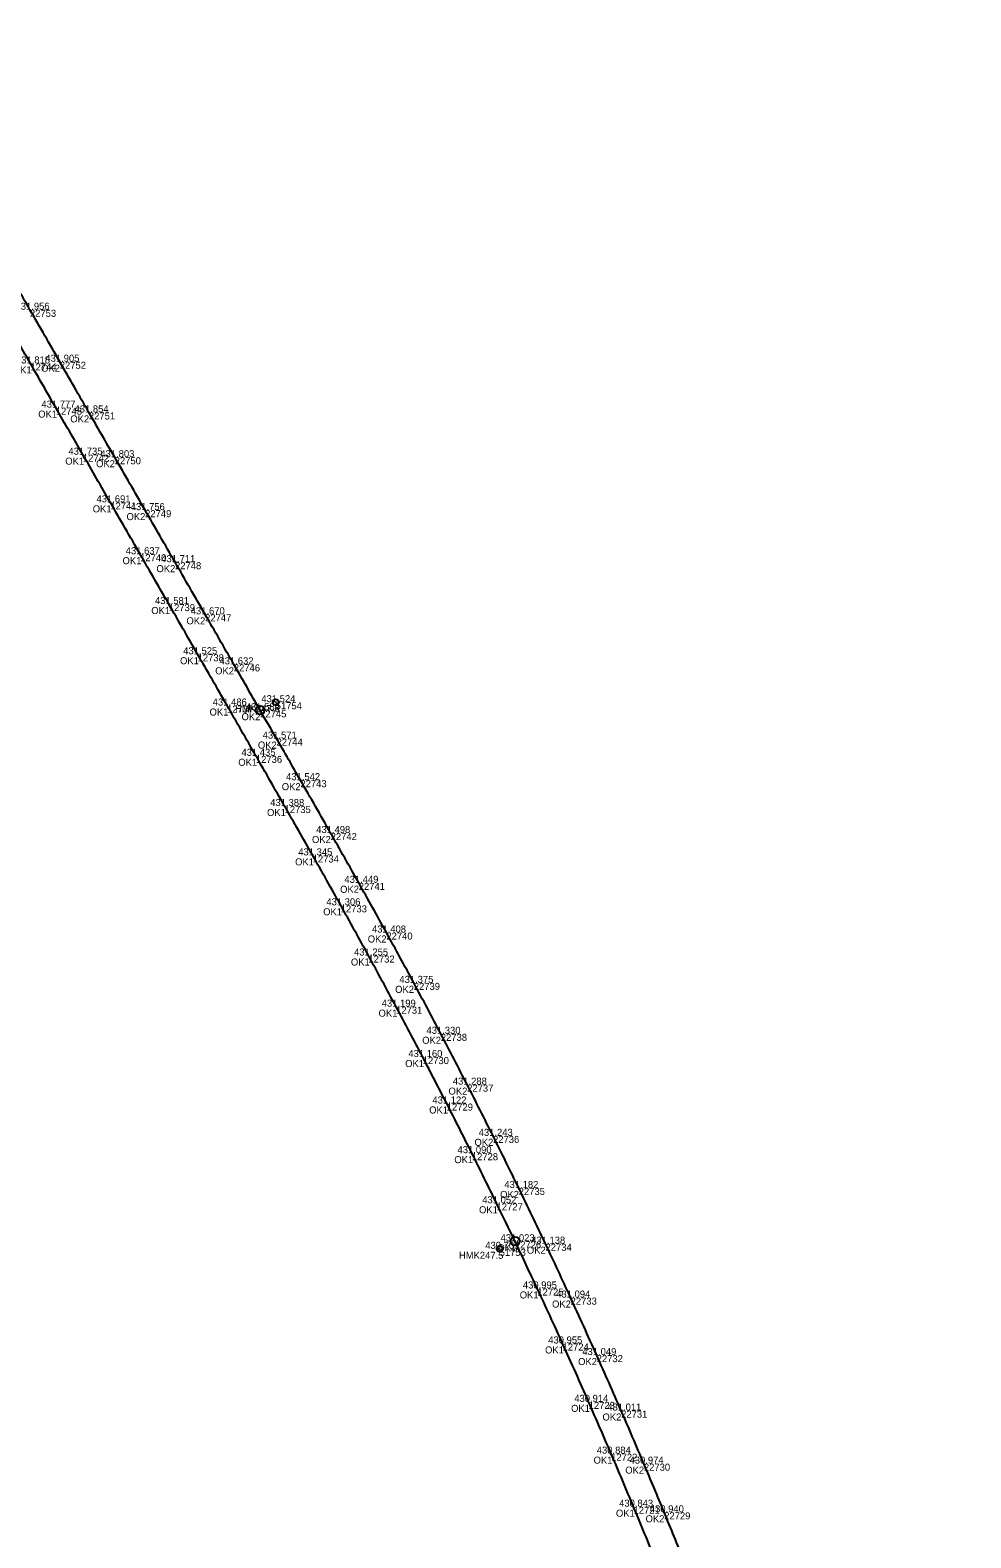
# Model space of a CAD drawing. Extents: x -678609 to -677678, y -1092434 to -1090394.
# Drawn here: x -678281 to -678120.7, y -1091923.5 to -1091666.6 of the extents above; entities that cross this region are included whole.
import ezdxf

# ---------------------------------------------------------------- set-up
doc = ezdxf.new("R2010")
doc.units = 0
for name, color, linetype in [('Vrstva 1', 7, 'Continuous'), ('Vrstva 60', 7, 'Continuous'), ('Vrstva 61', 7, 'Continuous'), ('Vrstva 62', 7, 'Continuous'), ('Vrstva 7', 7, 'Continuous')]:
    doc.layers.add(name, color=color, linetype=linetype)

msp = doc.modelspace()

# ---------------------------------------------------------------- linework, layer by layer
at = {"layer": 'Vrstva 1'}
for points in [[(-677965.5, -1092428.88), (-677967.8, -1092425.54), (-677972.06, -1092419.07), (-677977.32, -1092410.57), (-677981.84, -1092402.75), (-677986.7, -1092393.7), (-677991.48, -1092384.16), (-677995.99, -1092374.55), (-678000.17, -1092365.13), (-678004.02, -1092356.1), (-678007.82, -1092346.9), (-678011.74, -1092337.16), (-678015.49, -1092327.76), (-678018.88, -1092319.21), (-678022.34, -1092310.49), (-678025.4, -1092302.78), (-678026.46, -1092300.1), (-678028.08, -1092296.04), (-678031.51, -1092287.37), (-678035.08, -1092278.36), (-678038.67, -1092269.33), (-678042.19, -1092260.44), (-678045.92, -1092251.04), (-678049.17, -1092242.84), (-678052.72, -1092233.88), (-678056.52, -1092224.29), (-678060.13, -1092215.17), (-678063.85, -1092205.78), (-678067.58, -1092196.38), (-678071.23, -1092187.17), (-678074.63, -1092178.59), (-678078.07, -1092169.9), (-678081.19, -1092162.05), (-678084.71, -1092153.16), (-678085.21, -1092151.9), (-678088.66, -1092143.2), (-678090.49, -1092138.62), (-678093.75, -1092130.39), (-678097.35, -1092121.32), (-678101.03, -1092112.07), (-678104.65, -1092102.94), (-678108.08, -1092094.3), (-678111.85, -1092084.82), (-678115.34, -1092076.03), (-678118.88, -1092067.13), (-678122.7, -1092057.52), (-678126.45, -1092048.08), (-678130.12, -1092038.85), (-678134.04, -1092029), (-678137.7, -1092019.78), (-678141.32, -1092010.68), (-678144.94, -1092001.55), (-678148.54, -1091992.51), (-678152.22, -1091983.22), (-678155.78, -1091974.26), (-678159.37, -1091965.23), (-678163.15, -1091955.67), (-678166.8, -1091946.49), (-678170.64, -1091936.84), (-678174.45, -1091927.39), (-678178.21, -1091918.23), (-678182.03, -1091909.19), (-678185.86, -1091900.36), (-678190.3, -1091890.41), (-678194.61, -1091881.04), (-678198.42, -1091872.99), (-678201.55, -1091866.52), (-678205.76, -1091857.98), (-678210.04, -1091849.52), (-678214.14, -1091841.6), (-678218.68, -1091833.02), (-678223.39, -1091824.3), (-678228.11, -1091815.74), (-678232.89, -1091807.24), (-678237.68, -1091798.82), (-678242.57, -1091790.27), (-678247.48, -1091781.7), (-678252.5, -1091772.96), (-678257.41, -1091764.41), (-678262.3, -1091755.91), (-678267.38, -1091747.08), (-678272.06, -1091738.95), (-678276.67, -1091730.93), (-678281, -1091723.4), (-678285.64, -1091715.33), (-678290.57, -1091706.75), (-678295.17, -1091698.74), (-678299.18, -1091691.75), (-678304.61, -1091682.28), (-678309.18, -1091674.33), (-678309.94, -1091673.01), (-678310.56, -1091671.92), (-678316.58, -1091661.44), (-678321.55, -1091652.79), (-678326.07, -1091644.94), (-678331.1, -1091636.19), (-678336.13, -1091627.42), (-678341.16, -1091618.67), (-678346.24, -1091609.83), (-678351.2, -1091601.19), (-678356.26, -1091592.39), (-678361.27, -1091583.68), (-678366.29, -1091574.95), (-678371.38, -1091566.09), (-678376.48, -1091557.23), (-678380.94, -1091549.47), (-678384.95, -1091542.5), (-678389.88, -1091533.92), (-678391.41, -1091531.24), (-678395.31, -1091524.46), (-678398.31, -1091519.22), (-678402.19, -1091512.46), (-678406.98, -1091504.09), (-678412.06, -1091495.21), (-678417.07, -1091486.44), (-678421.59, -1091478.47), (-678426.39, -1091469.86), (-678431.19, -1091461.01), (-678435.59, -1091452.6), (-678440.54, -1091442.69), (-678444.84, -1091433.53), (-678448.93, -1091424.07), (-678452.67, -1091414.65), (-678456.15, -1091404.93), (-678459.23, -1091395.35), (-678461.83, -1091386.29), (-678463.33, -1091380.53), (-678465.42, -1091371.56), (-678467.31, -1091362.18), (-678468.87, -1091352.97), (-678470.15, -1091343.72), (-678471.15, -1091334.55), (-678471.89, -1091325.25), (-678472.38, -1091315.14), (-678472.53, -1091305.81), (-678472.39, -1091295.81), (-678471.98, -1091285.84), (-678471.34, -1091275.9), (-678470.53, -1091266.07), (-678469.61, -1091256.67), (-678468.46, -1091246.14), (-678467.2, -1091235.36), (-678466.06, -1091225.73), (-678464.97, -1091216.57), (-678463.79, -1091206.63), (-678462.6, -1091196.46), (-678461.48, -1091186.51), (-678460.53, -1091177.26), (-678460.07, -1091172.27), (-678459.6, -1091166.76), (-678458.93, -1091157.15), (-678458.54, -1091149.43), (-678458.26, -1091139.81), (-678458.24, -1091130.03), (-678458.46, -1091121.76), (-678458.96, -1091112.72), (-678459.56, -1091105.42), (-678460.03, -1091100.7), (-678460.44, -1091097.18), (-678461.42, -1091089.83), (-678462.92, -1091080.59), (-678464.88, -1091070.5), (-678465.87, -1091066.01), (-678468.24, -1091056.34), (-678470.96, -1091046.62), (-678473.78, -1091037.66), (-678476.99, -1091028.33), (-678480.32, -1091019.35), (-678483.95, -1091010.17), (-678487.77, -1091000.93), (-678492.09, -1090990.94), (-678495.91, -1090982.33), (-678497.23, -1090979.39), (-678500.62, -1090971.85), (-678504.73, -1090962.75), (-678508.48, -1090954.44), (-678512.89, -1090944.72), (-678517.19, -1090935.17), (-678521.19, -1090926.12), (-678525.01, -1090917.23), (-678528.92, -1090907.75), (-678532.48, -1090898.64), (-678535.33, -1090890.88), (-678536.98, -1090886.19), (-678540.17, -1090876.47), (-678543.06, -1090866.93), (-678545.5, -1090858.15), (-678547.9, -1090848.75), (-678550.22, -1090838.91), (-678552.41, -1090829.04), (-678553.21, -1090825.32), (-678554.73, -1090818.04), (-678556.89, -1090807.48), (-678558.82, -1090797.84), (-678560.45, -1090789.69), (-678561.92, -1090782.3), (-678563.92, -1090772.26), (-678565.62, -1090763.66), (-678567.4, -1090754.78), (-678569.24, -1090745.59), (-678571.09, -1090736.37), (-678573.01, -1090726.79), (-678574.94, -1090717.24), (-678576.9, -1090707.5), (-678578.79, -1090698.06), (-678580.69, -1090688.61), (-678582.63, -1090679), (-678584.57, -1090669.32), (-678586.61, -1090659.12), (-678588.6, -1090649.18), (-678590.47, -1090639.75), (-678592.41, -1090629.68), (-678594.08, -1090620.48), (-678595.57, -1090611.73), (-678596.96, -1090602.7), (-678598.18, -1090593.61), (-678598.92, -1090587.15), (-678599.86, -1090577.04), (-678600.45, -1090567.62), (-678600.74, -1090558.34), (-678600.75, -1090549.35), (-678600.47, -1090539.84), (-678599.88, -1090530.15), (-678599.15, -1090521.99), (-678598.15, -1090513.61), (-678597.58, -1090509.5), (-678596.28, -1090501.33), (-678594.49, -1090491.96), (-678592.38, -1090482.44), (-678589.8, -1090472.45), (-678586.94, -1090462.72), (-678583.68, -1090452.87), (-678579.95, -1090442.85), (-678576.03, -1090433.29), (-678571.81, -1090423.92), (-678567.43, -1090415), (-678562.94, -1090406.55), (-678558.47, -1090398.73), (-678556.06, -1090394.72)], [(-677960.41, -1092428.88), (-677963.18, -1092424.89), (-677968.58, -1092416.71), (-677973.83, -1092408.16), (-677978.65, -1092399.73), (-677983.17, -1092391.19), (-677987.58, -1092382.29), (-677991.66, -1092373.51), (-677995.54, -1092364.73), (-677999.48, -1092355.45), (-678003, -1092346.86), (-678006.4, -1092338.41), (-678008.07, -1092334.22), (-678011.06, -1092326.67), (-678014.79, -1092317.28), (-678018.17, -1092308.77), (-678021.37, -1092300.71), (-678022.15, -1092298.75), (-678025.47, -1092290.39), (-678029, -1092281.48), (-678032.79, -1092271.95), (-678036.42, -1092262.78), (-678040.08, -1092253.55), (-678043.64, -1092244.58), (-678046.8, -1092236.63), (-678050.2, -1092228.09), (-678054.05, -1092218.4), (-678057.87, -1092208.77), (-678061.64, -1092199.28), (-678064.93, -1092190.99), (-678068.51, -1092181.96), (-678072.17, -1092172.75), (-678076, -1092163.12), (-678079.45, -1092154.42), (-678082.71, -1092146.18), (-678084.42, -1092141.9), (-678086.21, -1092137.37), (-678089.72, -1092128.54), (-678093.32, -1092119.46), (-678097.16, -1092109.8), (-678100.72, -1092100.82), (-678103.85, -1092092.93), (-678107.35, -1092084.1), (-678110.92, -1092075.12), (-678114.45, -1092066.22), (-678118.41, -1092056.23), (-678122.02, -1092047.13), (-678125.64, -1092038.01), (-678129.26, -1092028.91), (-678132.87, -1092019.79), (-678136.68, -1092010.21), (-678140.28, -1092001.13), (-678143.89, -1091992.04), (-678147.54, -1091982.83), (-678151.47, -1091972.91), (-678155.19, -1091963.55), (-678158.5, -1091955.23), (-678162.14, -1091946.1), (-678165.94, -1091936.55), (-678169.61, -1091927.42), (-678172.98, -1091919.18), (-678176.44, -1091910.89), (-678180.32, -1091901.84), (-678184.49, -1091892.39), (-678188.93, -1091882.59), (-678193.21, -1091873.41), (-678197.78, -1091863.91), (-678202.15, -1091855.03), (-678206.56, -1091846.3), (-678211.05, -1091837.64), (-678215.66, -1091828.96), (-678220.33, -1091820.38), (-678225.04, -1091811.91), (-678229.83, -1091803.42), (-678234.98, -1091794.42), (-678239.05, -1091787.33), (-678241.84, -1091782.5), (-678246.33, -1091774.68), (-678251.23, -1091766.16), (-678256.35, -1091757.27), (-678261.45, -1091748.4), (-678266.63, -1091739.38), (-678271.03, -1091731.75), (-678275.99, -1091723.11), (-678281.08, -1091714.25), (-678285.98, -1091705.75), (-678290.88, -1091697.22), (-678295.45, -1091689.28), (-678300.01, -1091681.35), (-678300.91, -1091679.77), (-678305.04, -1091672.59), (-678308.7, -1091666.23), (-678313.56, -1091657.79), (-678316.07, -1091653.42), (-678316.99, -1091651.81), (-678322.04, -1091643.03), (-678327.11, -1091634.21), (-678332.27, -1091625.24), (-678337.32, -1091616.47), (-678342.33, -1091607.74), (-678347.33, -1091599.07), (-678352.43, -1091590.19), (-678357.51, -1091581.37), (-678362.52, -1091572.64), (-678367.56, -1091563.89), (-678372.6, -1091555.12), (-678377.69, -1091546.26), (-678382.67, -1091537.58), (-678387.77, -1091528.7), (-678389.17, -1091526.27), (-678390.17, -1091524.53), (-678393.18, -1091519.29), (-678397.89, -1091511.08), (-678402.8, -1091502.52), (-678408.01, -1091493.44), (-678412.94, -1091484.8), (-678417.67, -1091476.44), (-678422.72, -1091467.34), (-678425.17, -1091462.84), (-678430.24, -1091453.27), (-678432.13, -1091449.6), (-678436.36, -1091441.06), (-678440.36, -1091432.52), (-678444.3, -1091423.5), (-678448.14, -1091413.92), (-678451.67, -1091404.2), (-678454.52, -1091395.48), (-678456.78, -1091387.89), (-678459.36, -1091378.14), (-678461.46, -1091369.04), (-678463.24, -1091360.11), (-678464.77, -1091350.94), (-678466.09, -1091341.11), (-678467.05, -1091331.45), (-678467.74, -1091321.16), (-678468.06, -1091312.46), (-678468.13, -1091302.67), (-678467.92, -1091292.89), (-678467.75, -1091288.5), (-678467.24, -1091279.36), (-678466.65, -1091271.3), (-678465.8, -1091261.65), (-678464.83, -1091252.21), (-678464.22, -1091246.73), (-678463.17, -1091237.54), (-678462.04, -1091228.08), (-678460.89, -1091218.47), (-678459.79, -1091209.09), (-678458.69, -1091199.72), (-678457.61, -1091190.23), (-678456.66, -1091181.26), (-678456.28, -1091177.45), (-678455.95, -1091173.93), (-678455.21, -1091164.81), (-678454.58, -1091155.4), (-678454.12, -1091145.39), (-678453.9, -1091135.42), (-678453.98, -1091125.41), (-678454.4, -1091115.15), (-678455.19, -1091104.66), (-678455.67, -1091099.79), (-678456.77, -1091090.92), (-678457.24, -1091087.61), (-678458, -1091082.76), (-678459.78, -1091072.93), (-678461.55, -1091064.59), (-678463.75, -1091055.56), (-678466.3, -1091046.3), (-678469.14, -1091037.12), (-678472.3, -1091027.84), (-678475.73, -1091018.55), (-678479.35, -1091009.34), (-678482.78, -1091001.05), (-678486.39, -1090992.59), (-678490.2, -1090983.9), (-678491.75, -1090980.39), (-678492.98, -1090977.64), (-678496.18, -1090970.51), (-678500.43, -1090961.06), (-678504.03, -1090953.05), (-678508.11, -1090943.95), (-678512.14, -1090934.91), (-678516.17, -1090925.76), (-678520.15, -1090916.48), (-678524.11, -1090906.91), (-678527.45, -1090898.46), (-678529.96, -1090891.82), (-678532.42, -1090885.01), (-678535.4, -1090876.25), (-678538.3, -1090867), (-678541.15, -1090857.05), (-678543.63, -1090847.53), (-678545.8, -1090838.5), (-678548.27, -1090827.42), (-678548.84, -1090824.71), (-678550.27, -1090817.89), (-678552.12, -1090808.75), (-678554.09, -1090798.9), (-678556.12, -1090788.74), (-678556.56, -1090786.52), (-678557.74, -1090780.65), (-678559.41, -1090772.28), (-678561.24, -1090763.16), (-678563.16, -1090753.57), (-678565.21, -1090743.33), (-678567.13, -1090733.77), (-678569.13, -1090723.69), (-678570.72, -1090715.75), (-678572.44, -1090707.11), (-678574.33, -1090697.58), (-678575.5, -1090691.73), (-678576.87, -1090684.87), (-678578.68, -1090675.8), (-678580.42, -1090667.12), (-678582.34, -1090657.49), (-678584.31, -1090647.61), (-678586.28, -1090637.64), (-678588.2, -1090627.59), (-678589.96, -1090617.89), (-678591.58, -1090608.06), (-678593.06, -1090598.01), (-678594.31, -1090587.86), (-678595.29, -1090577.74), (-678595.95, -1090567.92), (-678596.27, -1090558.34), (-678596.28, -1090548.9), (-678595.99, -1090539.16), (-678595.39, -1090529.68), (-678594.52, -1090520.33), (-678593.84, -1090514.64), (-678593.37, -1090511.09), (-678591.87, -1090501.55), (-678590.51, -1090494.26), (-678588.64, -1090485.54), (-678587.94, -1090482.56), (-678585.53, -1090473.2), (-678582.78, -1090463.82), (-678579.92, -1090455.12), (-678576.62, -1090446.03), (-678572.81, -1090436.54), (-678568.84, -1090427.54), (-678564.34, -1090418.19), (-678559.62, -1090409.18), (-678555.08, -1090401.15), (-678551.2, -1090394.72)]]:
    msp.add_spline(points, degree=3, dxfattribs=at)
at = {"layer": 'Vrstva 60'}
for p, q in [((-678281, -1091723.4), (-678281, -1091723.4)), ((-678275.99, -1091723.11), (-678275.99, -1091723.11)), ((-678276.67, -1091730.93), (-678276.67, -1091730.93)), ((-678271.03, -1091731.75), (-678271.03, -1091731.75)), ((-678272.06, -1091738.95), (-678272.06, -1091738.95)), ((-678266.63, -1091739.38), (-678266.63, -1091739.38)), ((-678267.38, -1091747.08), (-678267.38, -1091747.08)), ((-678261.45, -1091748.4), (-678261.45, -1091748.4)), ((-678262.3, -1091755.91), (-678262.3, -1091755.91)), ((-678256.35, -1091757.27), (-678256.35, -1091757.27)), ((-678257.41, -1091764.41), (-678257.41, -1091764.41)), ((-678251.23, -1091766.16), (-678251.23, -1091766.16)), ((-678252.5, -1091772.96), (-678252.5, -1091772.96)), ((-678246.33, -1091774.68), (-678246.33, -1091774.68)), ((-678239.19, -1091781.13), (-678239.19, -1091781.13)), ((-678247.48, -1091781.7), (-678247.48, -1091781.7)), ((-678241.84, -1091782.5), (-678241.84, -1091782.5)), ((-678239.05, -1091787.33), (-678239.05, -1091787.33)), ((-678242.57, -1091790.27), (-678242.57, -1091790.27)), ((-678234.98, -1091794.42), (-678234.98, -1091794.42)), ((-678237.68, -1091798.82), (-678237.68, -1091798.82)), ((-678229.83, -1091803.42), (-678229.83, -1091803.42)), ((-678232.89, -1091807.24), (-678232.89, -1091807.24)), ((-678225.04, -1091811.91), (-678225.04, -1091811.91)), ((-678228.11, -1091815.74), (-678228.11, -1091815.74)), ((-678220.33, -1091820.38), (-678220.33, -1091820.38)), ((-678223.39, -1091824.3), (-678223.39, -1091824.3)), ((-678215.66, -1091828.96), (-678215.66, -1091828.96)), ((-678218.68, -1091833.02), (-678218.68, -1091833.02)), ((-678211.05, -1091837.64), (-678211.05, -1091837.64)), ((-678214.14, -1091841.6), (-678214.14, -1091841.6)), ((-678206.56, -1091846.3), (-678206.56, -1091846.3)), ((-678210.04, -1091849.52), (-678210.04, -1091849.52)), ((-678202.15, -1091855.03), (-678202.15, -1091855.03)), ((-678205.76, -1091857.98), (-678205.76, -1091857.98)), ((-678197.78, -1091863.91), (-678197.78, -1091863.91)), ((-678201.55, -1091866.52), (-678201.55, -1091866.52)), ((-678198.42, -1091872.99), (-678198.42, -1091872.99)), ((-678193.21, -1091873.41), (-678193.21, -1091873.41)), ((-678201.03, -1091874.28), (-678201.03, -1091874.28)), ((-678194.61, -1091881.04), (-678194.61, -1091881.04)), ((-678188.93, -1091882.59), (-678188.93, -1091882.59)), ((-678190.3, -1091890.41), (-678190.3, -1091890.41)), ((-678184.49, -1091892.39), (-678184.49, -1091892.39)), ((-678185.86, -1091900.36), (-678185.86, -1091900.36)), ((-678180.32, -1091901.84), (-678180.32, -1091901.84)), ((-678182.03, -1091909.19), (-678182.03, -1091909.19)), ((-678176.44, -1091910.89), (-678176.44, -1091910.89)), ((-678178.21, -1091918.23), (-678178.21, -1091918.23)), ((-678172.98, -1091919.18), (-678172.98, -1091919.18))]:
    msp.add_line(p, q, dxfattribs=at)
at = {"layer": 'Vrstva 7'}
for p, q in [((-678239.24, -1091781.13), (-678239.14, -1091781.13)), ((-678201.08, -1091874.28), (-678200.98, -1091874.28))]:
    msp.add_line(p, q, dxfattribs=at)
for centre, radius in [((-678239.19, -1091781.13), 0.5), ((-678241.84, -1091782.5), 0.75), ((-678198.42, -1091872.99), 0.75), ((-678201.03, -1091874.28), 0.5)]:
    msp.add_circle(centre, radius, dxfattribs=at)

# ---------------------------------------------------------------- texts
at = {"layer": 'Vrstva 60'}
for s, p in [('22753', (-678281.08, -1091715.45)), ('12744', (-678281, -1091724.6)), ('22752', (-678275.99, -1091724.31)), ('12743', (-678276.67, -1091732.13)), ('22751', (-678271.03, -1091732.95)), ('12742', (-678272.06, -1091740.15)), ('22750', (-678266.63, -1091740.58)), ('12741', (-678267.38, -1091748.28)), ('22749', (-678261.45, -1091749.6)), ('12740', (-678262.3, -1091757.11)), ('22748', (-678256.35, -1091758.47)), ('12739', (-678257.41, -1091765.61)), ('22747', (-678251.23, -1091767.36)), ('12738', (-678252.5, -1091774.16)), ('22746', (-678246.33, -1091775.88)), ('51754', (-678239.19, -1091782.33)), ('12737', (-678247.48, -1091782.9)), ('22745', (-678241.84, -1091783.7)), ('22744', (-678239.05, -1091788.53)), ('12736', (-678242.57, -1091791.47)), ('22743', (-678234.98, -1091795.62)), ('12735', (-678237.68, -1091800.02)), ('22742', (-678229.83, -1091804.62)), ('12734', (-678232.89, -1091808.44)), ('22741', (-678225.04, -1091813.11)), ('12733', (-678228.11, -1091816.94)), ('22740', (-678220.33, -1091821.58)), ('12732', (-678223.39, -1091825.5)), ('22739', (-678215.66, -1091830.16)), ('12731', (-678218.68, -1091834.22)), ('22738', (-678211.05, -1091838.84)), ('12730', (-678214.14, -1091842.8)), ('22737', (-678206.56, -1091847.5)), ('12729', (-678210.04, -1091850.72)), ('22736', (-678202.15, -1091856.23)), ('12728', (-678205.76, -1091859.18)), ('22735', (-678197.78, -1091865.11)), ('12727', (-678201.55, -1091867.72)), ('12726', (-678198.42, -1091874.19)), ('22734', (-678193.21, -1091874.61)), ('51753', (-678201.03, -1091875.48)), ('12725', (-678194.61, -1091882.24)), ('22733', (-678188.93, -1091883.79)), ('12724', (-678190.3, -1091891.61)), ('22732', (-678184.49, -1091893.59)), ('12723', (-678185.86, -1091901.56)), ('22731', (-678180.32, -1091903.04)), ('12722', (-678182.03, -1091910.39)), ('22730', (-678176.44, -1091912.09)), ('12721', (-678178.21, -1091919.43)), ('22729', (-678172.98, -1091920.38))]:
    msp.add_text(s, height=1.2, dxfattribs=at).set_placement(p)
at = {"layer": 'Vrstva 61'}
for s, p in [('431.956', (-678283.54, -1091714.25)), ('431.905', (-678278.45, -1091723.11)), ('431.818', (-678283.46, -1091723.4)), ('431.777', (-678279.12, -1091730.93)), ('431.854', (-678273.48, -1091731.75)), ('431.735', (-678274.52, -1091738.95)), ('431.803', (-678269.08, -1091739.38)), ('431.691', (-678269.74, -1091747.08)), ('431.756', (-678263.9, -1091748.4)), ('431.637', (-678264.75, -1091755.91)), ('431.711', (-678258.7, -1091757.27)), ('431.581', (-678259.77, -1091764.41)), ('431.670', (-678253.68, -1091766.16)), ('431.525', (-678254.96, -1091772.96)), ('431.632', (-678248.78, -1091774.68)), ('431.486', (-678249.93, -1091781.7)), ('431.524', (-678241.64, -1091781.13)), ('431.589', (-678244.29, -1091782.5)), ('431.571', (-678241.41, -1091787.33)), ('431.435', (-678245.03, -1091790.27)), ('431.542', (-678237.43, -1091794.42)), ('431.388', (-678240.13, -1091798.82)), ('431.498', (-678232.29, -1091803.42)), ('431.345', (-678235.35, -1091807.24)), ('431.449', (-678227.49, -1091811.91)), ('431.306', (-678230.56, -1091815.74)), ('431.408', (-678222.79, -1091820.38)), ('431.255', (-678225.84, -1091824.3)), ('431.375', (-678218.12, -1091828.96)), ('431.199', (-678221.13, -1091833.02)), ('431.330', (-678213.5, -1091837.64)), ('431.160', (-678216.59, -1091841.6)), ('431.288', (-678209.01, -1091846.3)), ('431.122', (-678212.49, -1091849.52)), ('431.243', (-678204.6, -1091855.03)), ('431.090', (-678208.21, -1091857.98)), ('431.182', (-678200.23, -1091863.91)), ('431.052', (-678203.99, -1091866.52)), ('430.709', (-678203.48, -1091874.28)), ('431.023', (-678200.87, -1091872.99)), ('431.138', (-678195.66, -1091873.41)), ('430.995', (-678197.07, -1091881.04)), ('431.094', (-678191.38, -1091882.59)), ('430.955', (-678192.75, -1091890.41)), ('431.049', (-678186.94, -1091892.39)), ('430.914', (-678188.31, -1091900.36)), ('431.011', (-678182.68, -1091901.84)), ('430.884', (-678184.48, -1091909.19)), ('430.974', (-678178.89, -1091910.89)), ('430.843', (-678180.67, -1091918.23)), ('430.940', (-678175.43, -1091919.18))]:
    msp.add_text(s, height=1.2, dxfattribs=at).set_placement(p)
at = {"layer": 'Vrstva 62'}
for s, p in [('OK1', (-678284, -1091725.1)), ('OK2', (-678279.17, -1091724.81)), ('OK1', (-678279.67, -1091732.63)), ('OK2', (-678274.2, -1091733.45)), ('OK1', (-678275.06, -1091740.65)), ('OK2', (-678269.81, -1091741.08)), ('OK1', (-678270.38, -1091748.78)), ('OK2', (-678264.62, -1091750.1)), ('OK1', (-678265.3, -1091757.61)), ('OK2', (-678259.52, -1091758.97)), ('OK1', (-678260.4, -1091766.11)), ('OK2', (-678254.41, -1091767.86)), ('OK1', (-678255.5, -1091774.66)), ('OK2', (-678249.51, -1091776.38)), ('OK1', (-678250.47, -1091783.4)), ('HMK247.6', (-678246.12, -1091782.83)), ('OK2', (-678245.02, -1091784.2)), ('OK2', (-678242.23, -1091789.03)), ('OK1', (-678245.57, -1091791.97)), ('OK2', (-678238.16, -1091796.12)), ('OK1', (-678240.67, -1091800.52)), ('OK2', (-678233.01, -1091805.12)), ('OK1', (-678235.89, -1091808.94)), ('OK2', (-678228.22, -1091813.61)), ('OK1', (-678231.11, -1091817.44)), ('OK2', (-678223.51, -1091822.08)), ('OK1', (-678226.38, -1091826)), ('OK2', (-678218.84, -1091830.66)), ('OK1', (-678221.67, -1091834.72)), ('OK2', (-678214.23, -1091839.34)), ('OK1', (-678217.13, -1091843.3)), ('OK2', (-678209.74, -1091848)), ('OK1', (-678213.04, -1091851.22)), ('OK2', (-678205.32, -1091856.73)), ('OK1', (-678208.75, -1091859.68)), ('OK2', (-678200.95, -1091865.61)), ('OK1', (-678204.54, -1091868.22)), ('OK1', (-678201.42, -1091874.69)), ('HMK247.5', (-678207.97, -1091875.98)), ('OK2', (-678196.39, -1091875.11)), ('OK1', (-678197.61, -1091882.74)), ('OK2', (-678192.1, -1091884.29)), ('OK1', (-678193.29, -1091892.11)), ('OK2', (-678187.66, -1091894.09)), ('OK1', (-678188.86, -1091902.06)), ('OK2', (-678183.5, -1091903.54)), ('OK1', (-678185.02, -1091910.89)), ('OK2', (-678179.62, -1091912.59)), ('OK1', (-678181.21, -1091919.93)), ('OK2', (-678176.16, -1091920.88))]:
    msp.add_text(s, height=1.2, dxfattribs=at).set_placement(p)

doc.saveas('drawing.dxf')
